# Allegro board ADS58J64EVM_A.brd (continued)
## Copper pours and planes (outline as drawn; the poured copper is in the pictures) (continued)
GND on TOP (solid shape): 32.99,107.81 33.36,107.81 33.36,108.83 33.64,108.83 33.64,107.81 33.92,107.81 33.92,106.06 33.64,106.06 33.64,105.03 33.36,105.03 33.36,106.06 32.99,106.06 32.99,105.03 32.71,105.03 32.71,106.06 32.42,106.06 32.42,107.81 32.71,107.81 32.71,108.83 32.99,108.83
GND on TOP (solid shape): 33.19,97.91 33.56,97.91 33.56,98.94 33.84,98.94 33.84,97.91 34.13,97.91 34.13,96.16 33.84,96.16 33.84,95.14 33.56,95.14 33.56,96.16 33.19,96.16 33.19,95.14 32.91,95.14 32.91,96.16 32.63,96.16 32.63,97.91 32.91,97.91 32.91,98.94 33.19,98.94
GND on TOP (solid shape): 38.86,65.9 39.23,65.9 39.23,66.92 39.51,66.92 39.51,65.9 39.79,65.9 39.79,64.15 39.51,64.15 39.51,63.12 39.23,63.12 39.23,64.15 38.86,64.15 38.86,63.12 38.58,63.12 38.58,64.15 38.29,64.15 38.29,65.9 38.58,65.9 38.58,66.92 38.86,66.92
GND on TOP: 104.52,0.38 104.52,32.77 0.38,32.77 0.38,112.9 0.76,113.28 65.79,113.28 66.29,112.78 66.29,96.14 66.93,95.5 75.96,95.5 75.96,93.18 77.64,93.18 77.64,95.5 86.49,95.5 87.25,96.27 87.25,112.9 87.63,113.28 91.26,113.28 91.26,113.03 92.46,113.03 92.46,110.84 94.14,110.84 94.14,113.03 95.33,113.03 95.33,113.28 109.85,113.28 109.85,113.03 113.92,113.03 113.92,113.28 128.42,113.28 128.42,113.03 129.63,113.03 129.63,110.75 131.31,110.75 131.31,113.03 132.46,113.03 132.46,113.28 136.27,113.28 136.53,113.03 136.53,96.27 137.29,95.5 146.14,95.5 146.14,93.49 147.82,93.49 147.82,95.5 156.84,95.5 157.48,96.14 157.48,113.03 157.73,113.28 172.09,113.28 172.34,113.03 172.34,0.38 ; 13 cut-outs
GND on TOP: 12.88,82.93 10.67,82.93 10.67,91.36 12.88,91.36
GND on BOTTOM: 104.52,0.38 104.52,32.77 0.38,32.77 0.38,112.9 0.76,113.28 65.79,113.28 66.29,112.78 66.29,96.14 66.93,95.5 86.49,95.5 87.25,96.27 87.25,112.9 87.63,113.28 91.26,113.28 91.26,113.03 95.33,113.03 95.33,113.28 109.85,113.28 109.85,113.03 111.05,113.03 111.05,111.11 112.73,111.11 112.73,113.03 113.92,113.03 113.92,113.28 128.42,113.28 128.42,113.03 132.46,113.03 132.46,113.28 136.27,113.28 136.53,113.03 136.53,96.27 137.29,95.5 156.84,95.5 157.48,96.14 157.48,113.03 157.73,113.28 172.09,113.28 172.34,113.03 172.34,0.38 ; 6 cut-outs
GND on L2-GND1: 0.38,112.9 0.76,113.28 65.79,113.28 66.29,112.78 66.29,96.14 66.93,95.5 86.49,95.5 87.25,96.27 87.25,112.9 87.63,113.28 91.26,113.28 91.26,113.03 95.33,113.03 95.33,113.28 109.85,113.28 109.85,113.03 113.92,113.03 113.92,113.28 128.42,113.28 128.42,113.03 132.46,113.03 132.46,113.28 136.27,113.28 136.53,113.03 136.53,96.27 137.29,95.5 156.84,95.5 157.48,96.14 157.48,113.03 157.73,113.28 172.09,113.28 172.34,113.03 172.34,0.38 104.52,0.38 104.52,32.77 0.38,32.77 ; 2 cut-outs
GND on L3-PWR1: 104.52,0.38 104.52,32.77 0.38,32.77 0.38,112.9 0.76,113.28 65.79,113.28 66.29,112.78 66.29,96.14 66.93,95.5 86.49,95.5 87.25,96.27 87.25,112.9 87.63,113.28 91.26,113.28 91.26,113.03 95.33,113.03 95.33,113.28 109.85,113.28 109.85,113.03 113.92,113.03 113.92,113.28 128.42,113.28 128.42,113.03 132.46,113.03 132.46,113.28 136.27,113.28 136.53,113.03 136.53,96.27 137.29,95.5 156.84,95.5 157.48,96.14 157.48,113.03 157.73,113.28 172.09,113.28 172.34,113.03 172.34,0.38
GND on L4-GND2, L5-GND3, L7-GND4: 0.38,112.9 0.76,113.28 65.79,113.28 66.29,112.78 66.29,96.14 66.93,95.5 86.49,95.5 87.25,96.27 87.25,112.9 87.63,113.28 91.26,113.28 91.26,113.03 95.33,113.03 95.33,113.28 109.85,113.28 109.85,113.03 113.92,113.03 113.92,113.28 128.42,113.28 128.42,113.03 132.46,113.03 132.46,113.28 136.27,113.28 136.53,113.03 136.53,96.27 137.29,95.5 156.84,95.5 157.48,96.14 157.48,113.03 157.73,113.28 172.09,113.28 172.34,113.03 172.34,0.38 104.52,0.38 104.52,32.77 0.38,32.77
GND on L6-PWR2: 0.38,112.9 0.76,113.28 65.79,113.28 66.29,112.78 66.29,96.14 66.93,95.5 86.49,95.5 87.25,96.27 87.25,112.9 87.63,113.28 91.26,113.28 91.26,113.03 95.33,113.03 95.33,113.28 109.85,113.28 109.85,113.03 113.92,113.03 113.92,113.28 128.42,113.28 128.42,113.03 132.46,113.03 132.46,113.28 136.27,113.28 136.53,113.03 136.53,96.27 137.29,95.5 156.84,95.5 157.48,96.14 157.48,113.03 157.73,113.28 172.09,113.28 172.34,113.03 172.34,0.38 104.52,0.38 104.52,32.77 0.38,32.77 ; 9 cut-outs
VCC1_VCC5_VCC6 on BOTTOM: 77.04,50.11 77.04,52.27 81.46,52.27 82.5,53.31 86.74,53.31 86.74,51.61 83.87,51.61 82.37,50.11
VCC1_VCC5_VCC6 on L3-PWR1: 77.01,49.4 77.01,53.21 84.58,53.21 84.58,64.64 89.28,64.64 89.28,49.4
VCC2_CG1 on TOP: 78.36,63.37 78.36,62.1 84.33,62.1 84.33,63.37
VCC2_CG1 on BOTTOM: 77.83,63.45 77.83,62.05 84.28,62.05 84.28,63.45
VCC3_SYSREF on BOTTOM: 77.8,60.78 77.8,59.44 80.77,59.44 80.77,60.78
VCC4_CG2 on BOTTOM: 77.8,58.17 77.8,57.02 83.03,57.02 83.44,57.43 83.44,58.17
VCC7_OSCOUT on BOTTOM: 86.87,50.04 86.87,53.21 88.14,53.21 88.14,52.07 88.52,51.69 88.52,50.04
VCC8_OSCIN on BOTTOM: 88.85,51.33 88.85,50.04 90.98,50.04 90.98,50.9 90.55,51.33
VCC8_VCC10 on TOP: 93.34,51.94 92.46,52.83 92.46,53.21 101.65,53.21 103.12,51.74 103.12,51.16 102.77,50.8 97.33,50.8 96.19,51.94
VCC8_VCC10 on BOTTOM: 86.87,46.84 86.87,48.56 93.73,48.56 94.23,49.07 94.23,51.94 93.34,51.94 93.17,52.12 93.17,52.4 94.08,53.31 103.12,53.31 103.12,51.05 101.8,51.05 101.37,51.49 98.22,51.49 98.15,51.41 98.15,50.8 95.68,50.8 95.68,48.13 94.39,46.84
VCC8_VCC10 on L6-PWR2: 86.87,46.84 86.87,48.56 92.28,48.56 92.46,48.74 92.46,52.65 103.12,52.65 103.12,50.22 95.68,50.22 95.68,48.13 94.39,46.84
VCC9_CP2 on BOTTOM: 91.77,50.85 91.77,50.04 93.47,50.04 93.47,51.46 93.07,51.46 91.57,52.96 90.55,52.96 90.55,52.07
VCC11_CG3 on TOP: 93.7,54.99 93.7,57.1 95.3,57.1 95.3,56.54 99.92,56.54 99.92,54.99
VCC11_CG3 on BOTTOM: 93.7,55.42 93.7,57.1 95.3,57.1 95.3,56.54 99.92,56.54 99.92,54.99 94.13,54.99
VCC12_CG0 on BOTTOM: 97.38,61.92 97.38,63.21 92.99,63.21 92.99,61.92
DRVDD1.15V on TOP, BOTTOM: 39.8,88.95 39.8,83.59 45.64,83.59 45.64,88.95
DRVDD1.15V on L6-PWR2: 39.5,70.36 39.5,89.41 48.39,89.41 48.39,80.52 105.74,80.52 106.25,81.03 118.24,81.03 118.24,76.02 116.97,74.75 116.97,70.36
IOVDD1.15V on TOP: 48.77,68.66 48.77,73.96 56.57,73.96 56.57,68.66
IOVDD1.15V on BOTTOM: 41.28,68.66 41.28,71.07 48.79,71.07 48.79,73.96 56.57,73.96 56.57,68.66
IOVDD1.15V on L3-PWR1: 48.39,72.14 48.39,79.12 118.87,79.12 118.87,68.45 52.07,68.45
VCPLD1.8V on TOP: 47.5,66.07 47.5,61.8 53.77,61.8 53.77,66.07
VCPLD1.8V on BOTTOM: 47.5,66.04 47.5,61.8 53.75,61.8 53.75,66.04
VCPLD1.8V on L3-PWR1: 38.23,47.5 38.23,51.31 41.4,51.31 41.4,57.02 47.12,57.02 47.12,64.14 54.74,64.14 54.74,58.93 71.5,58.93 71.5,47.5
N16918679 on TOP, BOTTOM: 109.07,37.85 109.07,39.42 101.07,39.42 101.07,37.85
N18101124 on TOP: 23.06,59.28 23.06,57.91 24.46,57.91 24.46,59.28
N18135910 on TOP: 34.19,106.83 34.19,105 42.85,105 42.85,107.16 41.4,107.16 41.07,106.83
N18135910 on BOTTOM: 37.44,106.83 37.44,105 42.85,105 42.85,107.16 41.4,107.16 41.07,106.83
N18153225 on BOTTOM: 11.81,40.51 11.81,44.32 14.99,44.32 15.37,44.7 15.37,46.61 16.64,47.88 22.22,47.88 22.22,46.61 18.41,46.61 17.65,45.85 17.65,44.2 19.76,42.09 19.76,40.51
N18272382 on TOP: 32.54,88.44 32.54,85.37 37.59,85.37 37.59,88.44
N18272382 on BOTTOM: 35.23,88.44 35.23,85.37 37.59,85.37 37.59,88.44
N18433762 on TOP: 12.55,96.22 11.1,96.22 11.1,93.19 9.47,93.19 9.47,96.22 8.74,96.22 8.74,97.99 12.55,97.99
N18433762 on BOTTOM: 12.55,96.22 11.05,96.22 11.05,93.22 9.53,93.22 9.53,96.22 8.74,96.22 8.74,97.99 12.55,97.99
N19072087 on BOTTOM: 6.93,45.29 6.93,46.61 13.08,46.61 13.08,44.7 13.06,44.68 11.81,44.68 11.79,44.7 11.79,45.29
N19631315 on TOP: 18.64,74.19 18.64,76.73 14.86,76.73 13.64,75.51 13.64,74.19 12.29,74.19 12.24,74.14 12.24,73.63 11.35,73.63 11.35,72.49 12.7,72.49 12.7,70.64 16.99,70.64 16.99,72.54
N19818342 on TOP: 34.39,96.9 34.39,93.52 41.5,93.52 41.5,96.9
N19818342 on BOTTOM: 37.26,96.9 37.26,93.52 40.82,93.52 40.82,96.9
N19839464 on BOTTOM: 33.83,70.54 33.83,74.9 34.65,75.72 34.65,78.77 35.41,78.77 35.84,79.2 36.78,79.2 36.78,77.88 36.14,77.24 36.14,76.56 36.16,76.54 36.16,74.99 35.56,74.4 35.56,70.54
N19839484 on TOP: 36.47,70.48 36.47,79.2 37.44,79.2 37.44,70.48
N19839498 on TOP: 40.08,76.1 40.08,72.29 44.78,72.29 44.78,76.1
N19839498 on BOTTOM: 38.68,70.51 38.68,74.07 40.08,75.46 44.78,75.46 44.78,72.26 40.72,72.26 40.56,72.11 40.56,70.51
N20038355 on TOP: 53.21,78.16 53.21,74.93 59.33,74.93 59.33,78.16 57.48,78.16 56.64,78.99 55.42,78.99 55.42,78.23 55.35,78.16
N20038355 on BOTTOM: 53.7,78.11 53.7,74.93 59.33,74.93 59.33,78.11
N20039339 on TOP: 40.06,64.85 40.06,62.76 42.65,62.76 42.98,62.43 42.98,61.7 45.21,61.7 45.21,64.85
N20039339 on BOTTOM: 45.21,64.87 45.21,61.7 43.15,61.7 43.15,64.87

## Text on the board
BOTTOM: LAYER 8 (BOTTOM SIDE)
Ref Des/Assembly Bottom: BOTTOM ASSEMBLY
Package Geometry/Pastemask Bottom: PASTEMASK BOTTOM
Ref Des/Silkscreen Bottom: GND | SILKSCREEN BOTTOM
User.Comments: * | F1 | E1 | H1 | G1 | J1 | J40 | H40 | G40 | F40 | E40 | L2 | C104 | R96 | FB10 | C91 | C95 | C93 | C163 | D1 | C1 | B1 | A1 | K1 | K40 | D40 | C40 | B40 | A40 | K6 | A6 | K11 | A11 | K16 | A16 | K21 | A21 | K26 | A26 | K31 | A31 | K36 | A36 | GND | J6 | U15 | C8 | ADC CLK IN | C43 | FB2 | T5 | C61 | FB8 | C58 | C101 | C2 | FB9 | R106 | C87 | C164 | C4 | R105 | C51 | R82 | FB6 | FB5 | FB7 | C63 | C62 | C64 | R86 | R85 | R57 | R111 | R110 | R175 | C184 | C155 | C153 | C165 | L3 | R37 | R181 | C166 | L4 | C154 | C162 | R174 | C196 | R32 | R47 | R178 | R162 | C194 | C195 | U7 | R189 | R126 | C204 | C205 | C206 | C201 | R84 | R36 | R18 | C10 | C11 | C94 | C81 | C84 | C90 | C85 | C59 | C57 | FB4 | FB11 | C5 | FB3 | C88 | C102 | C174 | C173 | C117 | C282 | C279 | C156 | C273 | C272 | C132 | C110 | C131 | C285 | C145 | C271 | C142 | R113 | R33 | R177 | C123 | C148 | C182 | R176 | R41 | R28 | R161 | R188 | R29 | R125 | C96 | R81 | R35 | R39 | R170 | R19 | R20 | C152 | C200 | C277 | ADS5XJ64EVM  REV A | SOLDERMASK TOP | SOLDERMASK BOTTOM | J3 | Q1
TOP: LAYER 1  (TOP SIDE)
Package Geometry/Pastemask Top: PASTEMASK TOP
Ref Des/Silkscreen Top: SDIO | SDO | SEN | SCK | TMS | TCK | TDO | TDI | J6 | EXT_ADC_CLK | FMC CONNECTOR | J3 | UL94V-0 | SILKSCREEN TOP | FMC | USB | ADS54J64EVM | LMK04828 | ADS5XJ64 | REV A
L2-GND1: LAYER 2  (GND1)
L3-PWR1: LAYER 3  (PWR1)
L4-GND2: LAYER 4  (GND2)
L5-GND3: LAYER 5  (GND3)
L6-PWR2: LAYER 6  (PWR2)
L7-GND4: LAYER 7  (GND4)
User.45: 03-03-2016 | TOP SIDE | BOTTOM SIDE | VIA HOLE SIZES 8,10,15 AND 12MILS APPLY AFTER PLATING. TOLERANCE TO BE +.003/-.010. | 19. ALL 8,10,12 & 15mil DRILLS NEED TO BE PLATED OVER TO HAVE FILL AND FLAT FINISH ON BOTH SIDES. | OUTER LAYERS USING A 20mil TRACE WIDTH SHALL BE  50ohms SINGLE ENDED, +/- 10% TOLERANCE. | VIASYSTEMS STACKUP JOB NAME: DAC38J84_RO4350 | FIGURE | SIZE | 6.0 | 8.0 | 10.0 | 12.0 | 15.0 | 38.0 | 62.0 | 67.0 | 106.0 | 120.0 | 125.0 | 140.0 | 35.0 | 50.0 | DRILL CHART: TOP to BOTTOM | ALL UNITS ARE IN MILS | PLATED | NON-PLATED | QTY | 82 | 650 | 2754 | 19 | 281 | 8 | 30 | 21 | 4 | 2 | 6 | 1 | THIS STACK UP DETAIL IS FOR REFERENCE ONLY | A
